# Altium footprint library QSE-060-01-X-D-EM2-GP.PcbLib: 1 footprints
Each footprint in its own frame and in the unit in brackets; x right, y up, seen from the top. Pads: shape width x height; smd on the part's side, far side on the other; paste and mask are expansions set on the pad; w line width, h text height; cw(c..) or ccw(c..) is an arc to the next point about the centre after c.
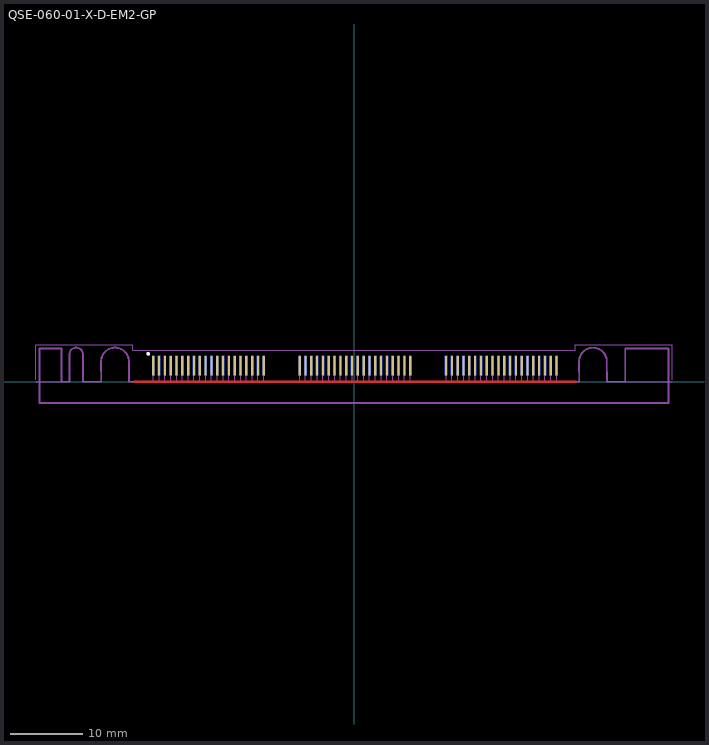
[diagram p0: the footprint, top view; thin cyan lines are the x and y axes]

## QSE-060-01-X-D-EM2-GP [mil] "0.80mm pitch, 140 pin, high speed socket strip; differential"
height 142.91
pads (120):
  rect 12.01x105 smd far side mask+0: 1(-1086.75,87.5) 3(-1055.25,87.5) 5(-1023.75,87.5) 7(-992.26,87.5) 9(-960.76,87.5) 11(-929.27,87.5) 13(-897.77,87.5) 15(-866.27,87.5) 17(-834.78,87.5) 19(-803.28,87.5) 21(-771.79,87.5) 23(-740.29,87.5) 25(-708.79,87.5) 27(-677.3,87.5) 29(-645.8,87.5) 31(-614.31,87.5) 33(-582.81,87.5) 35(-551.31,87.5) 37(-519.82,87.5) 39(-488.32,87.5) 41(-294.23,87.5) 43(-262.73,87.5) 45(-231.23,87.5) 47(-199.74,87.5) 49(-168.24,87.5) 51(-136.75,87.5) 53(-105.25,87.5) 55(-73.75,87.5) 57(-42.26,87.5) 59(-10.76,87.5) 61(20.73,87.5) 63(52.23,87.5) 65(83.73,87.5) 67(115.22,87.5) 69(146.72,87.5) 71(178.21,87.5) 73(209.71,87.5) 75(241.21,87.5) 77(272.7,87.5) 79(304.2,87.5) 81(498.29,87.5) 83(529.79,87.5) 85(561.29,87.5) 87(592.78,87.5) 89(624.28,87.5) 91(655.77,87.5) 93(687.27,87.5) 95(718.77,87.5) 97(750.26,87.5) 99(781.76,87.5) 101(813.25,87.5) 103(844.75,87.5) 105(876.25,87.5) 107(907.74,87.5) 109(939.24,87.5) 111(970.73,87.5) 113(1002.23,87.5) 115(1033.73,87.5) 117(1065.22,87.5) 119(1096.72,87.5)
  rect 12.01x105 smd mask+0: 2(-1086.75,87.5) 4(-1055.25,87.5) 6(-1023.75,87.5) 8(-992.26,87.5) 10(-960.76,87.5) 12(-929.27,87.5) 14(-897.77,87.5) 16(-866.27,87.5) 18(-834.78,87.5) 20(-803.28,87.5) 22(-771.79,87.5) 24(-740.29,87.5) 26(-708.79,87.5) 28(-677.3,87.5) 30(-645.8,87.5) 32(-614.31,87.5) 34(-582.81,87.5) 36(-551.31,87.5) 38(-519.82,87.5) 40(-488.32,87.5) 42(-294.23,87.5) 44(-262.73,87.5) 46(-231.23,87.5) 48(-199.74,87.5) 50(-168.24,87.5) 52(-136.75,87.5) 54(-105.25,87.5) 56(-73.75,87.5) 58(-42.26,87.5) 60(-10.76,87.5) 62(20.73,87.5) 64(52.23,87.5) 66(83.73,87.5) 68(115.22,87.5) 70(146.72,87.5) 72(178.21,87.5) 74(209.71,87.5) 76(241.21,87.5) 78(272.7,87.5) 80(304.2,87.5) 82(498.29,87.5) 84(529.79,87.5) 86(561.29,87.5) 88(592.78,87.5) 90(624.28,87.5) 92(655.77,87.5) 94(687.27,87.5) 96(718.77,87.5) 98(750.26,87.5) 100(781.76,87.5) 102(813.25,87.5) 104(844.75,87.5) 106(876.25,87.5) 108(907.74,87.5) 110(939.24,87.5) 112(970.73,87.5) 114(1002.23,87.5) 116(1033.73,87.5) 118(1065.22,87.5) 120(1096.72,87.5)
Top Layer:
  region: -1192.75,5 1202.72,5 1202.72,-5 -1192.75,-5
Top Overlay:
  circle w9.84: c-1114.17,151.57 r4.92
Top Paste:
  region: -1192.75,10 1202.72,10 1202.72,-5 -1192.75,-5
Top Solder:
  lines w5: -1086.75,87.5 -1086.75,139.98 ; -1055.25,87.5 -1055.25,139.98 ; -1023.75,87.5 -1023.75,139.98 ; -992.26,87.5 -992.26,139.98 ; -960.76,87.5 -960.76,139.98 ; -929.27,87.5 -929.27,139.98 ; -897.77,87.5 -897.77,139.98 ; -866.27,87.5 -866.27,139.98 ; -834.78,87.5 -834.78,139.98 ; -803.28,87.5 -803.28,139.98 ; -771.79,87.5 -771.79,139.98 ; -740.29,87.5 -740.29,139.98 ; -708.79,87.5 -708.79,139.98 ; -677.3,87.5 -677.3,139.98 ; -645.8,87.5 -645.8,139.98 ; -614.31,87.5 -614.31,139.98 ; -582.81,87.5 -582.81,139.98 ; -551.31,87.5 -551.31,139.98 ; -519.82,87.5 -519.82,139.98 ; -488.32,87.5 -488.32,139.98 ; -294.23,87.5 -294.23,139.98 ; -262.73,87.5 -262.73,139.98 ; -231.23,87.5 -231.23,139.98 ; -199.74,87.5 -199.74,139.98 ; -168.24,87.5 -168.24,139.98 ; -136.75,87.5 -136.75,139.98 ; -105.25,87.5 -105.25,139.98 ; -73.75,87.5 -73.75,139.98 ; -42.26,87.5 -42.26,139.98 ; -10.76,87.5 -10.76,139.98 ; 20.73,87.5 20.73,139.98 ; 52.23,87.5 52.23,139.98 ; 83.73,87.5 83.73,139.98 ; 115.22,87.5 115.22,139.98 ; 146.72,87.5 146.72,139.98 ; 178.21,87.5 178.21,139.98 ; 209.71,87.5 209.71,139.98 ; 241.21,87.5 241.21,139.98 ; 272.7,87.5 272.7,139.98 ; 304.2,87.5 304.2,139.98 ; 498.29,87.5 498.29,139.98 ; 529.79,87.5 529.79,139.98 ; 561.29,87.5 561.29,139.98 ; 592.78,87.5 592.78,139.98 ; 624.28,87.5 624.28,139.98 ; 655.77,87.5 655.77,139.98 ; 687.27,87.5 687.27,139.98 ; 718.77,87.5 718.77,139.98 ; 750.26,87.5 750.26,139.98 ; 781.76,87.5 781.76,139.98 ; 813.25,87.5 813.25,139.98 ; 844.75,87.5 844.75,139.98 ; 876.25,87.5 876.25,139.98 ; 907.74,87.5 907.74,139.98 ; 939.24,87.5 939.24,139.98 ; 970.73,87.5 970.73,139.98 ; 1002.23,87.5 1002.23,139.98 ; 1033.73,87.5 1033.73,139.98 ; 1065.22,87.5 1065.22,139.98 ; 1096.72,87.5 1096.72,139.98
Bottom Solder:
  lines w5: -1086.75,87.5 -1086.75,139.98 ; -1055.25,87.5 -1055.25,139.98 ; -1023.75,87.5 -1023.75,139.98 ; -992.26,87.5 -992.26,139.98 ; -960.76,87.5 -960.76,139.98 ; -929.27,87.5 -929.27,139.98 ; -897.77,87.5 -897.77,139.98 ; -866.27,87.5 -866.27,139.98 ; -834.78,87.5 -834.78,139.98 ; -803.28,87.5 -803.28,139.98 ; -771.79,87.5 -771.79,139.98 ; -740.29,87.5 -740.29,139.98 ; -708.79,87.5 -708.79,139.98 ; -677.3,87.5 -677.3,139.98 ; -645.8,87.5 -645.8,139.98 ; -614.31,87.5 -614.31,139.98 ; -582.81,87.5 -582.81,139.98 ; -551.31,87.5 -551.31,139.98 ; -519.82,87.5 -519.82,139.98 ; -488.32,87.5 -488.32,139.98 ; -294.23,87.5 -294.23,139.98 ; -262.73,87.5 -262.73,139.98 ; -231.23,87.5 -231.23,139.98 ; -199.74,87.5 -199.74,139.98 ; -168.24,87.5 -168.24,139.98 ; -136.75,87.5 -136.75,139.98 ; -105.25,87.5 -105.25,139.98 ; -73.75,87.5 -73.75,139.98 ; -42.26,87.5 -42.26,139.98 ; -10.76,87.5 -10.76,139.98 ; 20.73,87.5 20.73,139.98 ; 52.23,87.5 52.23,139.98 ; 83.73,87.5 83.73,139.98 ; 115.22,87.5 115.22,139.98 ; 146.72,87.5 146.72,139.98 ; 178.21,87.5 178.21,139.98 ; 209.71,87.5 209.71,139.98 ; 241.21,87.5 241.21,139.98 ; 272.7,87.5 272.7,139.98 ; 304.2,87.5 304.2,139.98 ; 498.29,87.5 498.29,139.98 ; 529.79,87.5 529.79,139.98 ; 561.29,87.5 561.29,139.98 ; 592.78,87.5 592.78,139.98 ; 624.28,87.5 624.28,139.98 ; 655.77,87.5 655.77,139.98 ; 687.27,87.5 687.27,139.98 ; 718.77,87.5 718.77,139.98 ; 750.26,87.5 750.26,139.98 ; 781.76,87.5 781.76,139.98 ; 813.25,87.5 813.25,139.98 ; 844.75,87.5 844.75,139.98 ; 876.25,87.5 876.25,139.98 ; 907.74,87.5 907.74,139.98 ; 939.24,87.5 939.24,139.98 ; 970.73,87.5 970.73,139.98 ; 1002.23,87.5 1002.23,139.98 ; 1033.73,87.5 1033.73,139.98 ; 1065.22,87.5 1065.22,139.98 ; 1096.72,87.5 1096.72,139.98
Mechanical 12:
  lines w0.04: -1722.44,0 -1540.25,0 -1540.25,148.5 ; -1467.25,148.5 -1467.25,0 -1368.75,0 -1368.75,110 ; -1218.75,110 -1218.75,0 1218.75,0 1218.75,110 ; 1368.75,110 1368.75,0 1722.44,0
Mechanical 13:
  circle w9.84: c-1114.17,151.57 r4.92
  lines w3.94: -1086.75,5 -1086.75,87.5 ; -1055.25,5 -1055.25,87.5 ; -1023.75,5 -1023.75,87.5 ; -992.26,5 -992.26,87.5 ; -960.76,5 -960.76,87.5 ; -929.27,5 -929.27,87.5 ; -897.77,5 -897.77,87.5 ; -866.27,5 -866.27,87.5 ; -834.78,5 -834.78,87.5 ; -803.28,5 -803.28,87.5 ; -771.79,5 -771.79,87.5 ; -740.29,5 -740.29,87.5 ; -708.79,5 -708.79,87.5 ; -677.3,5 -677.3,87.5 ; -645.8,5 -645.8,87.5 ; -614.31,5 -614.31,87.5 ; -582.81,5 -582.81,87.5 ; -551.31,5 -551.31,87.5 ; -519.82,5 -519.82,87.5 ; -488.32,5 -488.32,87.5 ; -294.23,5 -294.23,87.5 ; -262.73,5 -262.73,87.5 ; -231.23,5 -231.23,87.5 ; -199.74,5 -199.74,87.5 ; -168.24,5 -168.24,87.5 ; -136.75,5 -136.75,87.5 ; -105.25,5 -105.25,87.5 ; -73.75,5 -73.75,87.5 ; -42.26,5 -42.26,87.5 ; -10.76,5 -10.76,87.5 ; 20.73,5 20.73,87.5 ; 52.23,5 52.23,87.5 ; 83.73,5 83.73,87.5 ; 115.22,5 115.22,87.5 ; 146.72,5 146.72,87.5 ; 178.21,5 178.21,87.5 ; 209.71,5 209.71,87.5 ; 241.21,5 241.21,87.5 ; 272.7,5 272.7,87.5 ; 304.2,5 304.2,87.5 ; 498.29,5 498.29,87.5 ; 529.79,5 529.79,87.5 ; 561.29,5 561.29,87.5 ; 592.78,5 592.78,87.5 ; 624.28,5 624.28,87.5 ; 655.77,5 655.77,87.5 ; 687.27,5 687.27,87.5 ; 718.77,5 718.77,87.5 ; 750.26,5 750.26,87.5 ; 781.76,5 781.76,87.5 ; 813.25,5 813.25,87.5 ; 844.75,5 844.75,87.5 ; 876.25,5 876.25,87.5 ; 907.74,5 907.74,87.5 ; 939.24,5 939.24,87.5 ; 970.73,5 970.73,87.5 ; 1002.23,5 1002.23,87.5 ; 1033.73,5 1033.73,87.5 ; 1065.22,5 1065.22,87.5 ; 1096.72,5 1096.72,87.5
  lines w10: -1703.25,-115.08 -1703.25,180 -1583.25,180 -1583.25,0 -1541,0 -1540.25,148.5 cw(c-1503.75,148.5) -1467.25,148.5 -1467,0 -1368,0 -1368.75,110 cw(c-1293.75,110) -1218.75,110 -1218,0 1219,0 1218.75,110 cw(c1293.62,110) 1368.5,110 1369,0 1468.25,0 1468.25,180 1703.25,180 1703.25,-115.08 -1703.25,-115.08
  text ".Designator" at 0,0 h60
Mechanical 15:
  lines w1.97: -1722.44,9.84 -1722.44,199.61 -1196.85,199.61 -1196.85,171.26 1196.85,171.26 1196.85,199.61 1722.44,199.61 1722.44,9.84
Drill Drawing:
  lines w0.04: -1540.25,148.5 cw(c-1503.75,148.5) -1467.25,148.5 ; -1368.75,110 cw(c-1293.75,110) -1218.75,110 ; 1218.75,110 cw(c1293.75,110) 1368.75,110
